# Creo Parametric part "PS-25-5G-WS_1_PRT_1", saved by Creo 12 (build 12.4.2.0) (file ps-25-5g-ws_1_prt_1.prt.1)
Units: Custom; MM, KILOGRAM, SECS

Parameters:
  PTC_WM_ITERATION = "0"
  PTC_WM_VERSION = "-.0"
  PTC_WM_LIFECYCLE_STATE = "In Work"
  PTC_WM_LIFECYCLE = "MO_CADDocument"
  PTC_WM_CREATED_BY = "Maximilian Roepper (Z0017RMS: MO)"
  PTC_WM_CREATED_ON = "18-Sep-26 11:36:42 AM"
  PTC_WM_MODIFIED_BY = "Maximilian Roepper (Z0017RMS: MO)"
  PTC_WM_MODIFIED_ON = "18-Sep-26 11:36:46 AM"
  PDMLINKNUMBER = "PDM000071455244"
  PTC_WM_NAME = "ps-25-5g-ws_1_prt_1.prt"
  PTC_WM_NUMBER = "PDM000071455244"

Other parameters: WEIGHT, WEIGHT_FACTOR, WEIGHT_ADD, _MASS_TEMP, _DIFF_TEMP, MC_ERRORS, SUPPLIER

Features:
  1. coordinate system
  2. datum plane "PRT_YZ"
  3. datum plane "PRT_XY"
  4. datum plane "PRT_XZ"
  5. coordinate system
  6. datum axis
  7. datum axis
  8. datum axis
  9. coordinate system
  10. imported feature
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
Other named items: PRT, SIEMENS_MO, DRW_VIEW_ORG, PRT_X, PRT_Y, PRT_Z, CS0, ROUGH_GROB

Layers: 00_STD_CSYS-KSYS, 01_STD_PLANES-EBENEN, 02_STD_AXES-ACHSEN, 03_STD_CSYS-KSYS, 24_IMPORT_FEAT-IMPORT_KE

Surfaces: 124 plane, 2 cylinder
